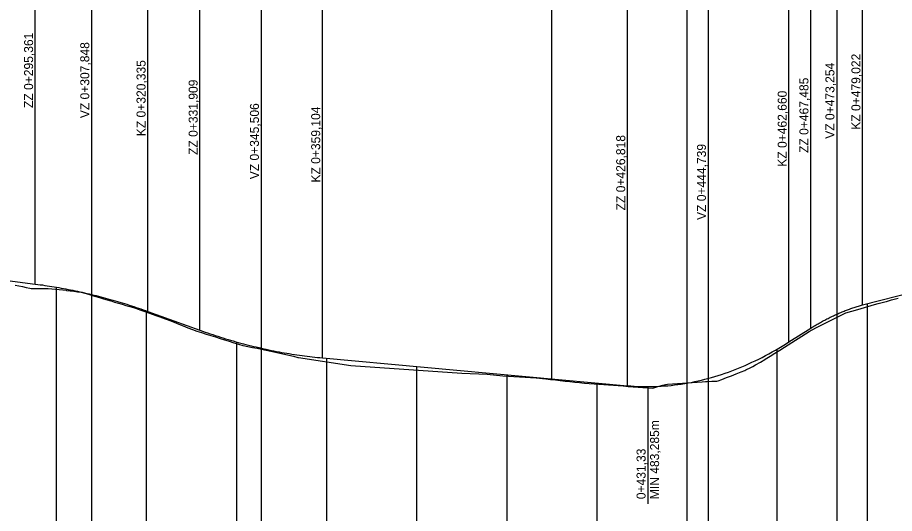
# Model space of a CAD drawing. Extents: x -632716 to -629545, y -1094726 to -1088285.
# Drawn here: x -632192 to -631997.4, y -1090910.5 to -1090800.4 of the extents above; entities that cross this region are included whole.
import ezdxf

# ---------------------------------------------------------------- set-up
doc = ezdxf.new("R2010")
doc.units = 0
for name, color, linetype in [('20', 7, 'Continuous'), ('Default', 7, 'Continuous'), ('SKLONY_NIVELETA', 7, 'Continuous'), ('SKLONY_POPIS', 7, 'Continuous'), ('TECNY_NIVELETA', 7, 'Continuous'), ('VOZOVKA', 7, 'Continuous')]:
    doc.layers.add(name, color=color, linetype=linetype)

msp = doc.modelspace()

# ---------------------------------------------------------------- linework, layer by layer
at = {"layer": '20'}
for points in [[(-632183.46, -1090860.27), (-632183.46, -1090965.2), (-632183.46, -1091015.2), (-632183.46, -1090955.2)], [(-632163.46, -1090865.55), (-632163.46, -1090965.2), (-632163.46, -1091015.2), (-632163.46, -1090955.2)], [(-632003.46, -1090863.98), (-632003.46, -1090965.2), (-632003.46, -1091015.2), (-632003.46, -1090955.2)], [(-632143.46, -1090872.42), (-632143.46, -1090965.2), (-632143.46, -1091015.2), (-632143.46, -1090955.2)], [(-632023.46, -1090874.05), (-632023.46, -1090965.2), (-632023.46, -1091015.2), (-632023.46, -1090955.2)], [(-632123.46, -1090876.05), (-632123.46, -1090965.2), (-632123.46, -1091015.2), (-632123.46, -1090955.2)], [(-632103.46, -1090877.87), (-632103.46, -1090965.2), (-632103.46, -1091015.2), (-632103.46, -1090955.2)], [(-632083.46, -1090879.7), (-632083.46, -1090965.2), (-632083.46, -1091015.2), (-632083.46, -1090955.2)], [(-632063.46, -1090881.52), (-632063.46, -1090965.2), (-632063.46, -1091015.2), (-632063.46, -1090955.2)], [(-632043.46, -1090881.59), (-632043.46, -1090965.2), (-632043.46, -1091015.2), (-632043.46, -1090955.2)]]:
    msp.add_lwpolyline(points, dxfattribs=at)
at = {"layer": 'Default'}
for p, q in [((-632320.69, -1090842.77), (-632188.1, -1090859.58)), ((-632320.69, -1090842.77), (-632188.1, -1090859.58)), ((-632004.44, -1090864.23), (-631946.1, -1090848.93)), ((-632004.44, -1090864.23), (-631946.1, -1090848.93)), ((-632163.13, -1090865.67), (-632151.56, -1090869.83)), ((-632163.13, -1090865.67), (-632151.56, -1090869.83)), ((-632020.8, -1090872.44), (-632015.98, -1090869.39)), ((-632020.8, -1090872.44), (-632015.98, -1090869.39)), ((-632124.36, -1090875.97), (-632056.65, -1090882.14)), ((-632124.36, -1090875.97), (-632056.65, -1090882.14))]:
    msp.add_line(p, q, dxfattribs=at)
for points in [[(-632188.1, -1090859.58), (-632187.58, -1090859.65), (-632187.06, -1090859.72), (-632186.54, -1090859.79), (-632186.02, -1090859.87), (-632185.5, -1090859.95), (-632184.98, -1090860.03), (-632184.46, -1090860.11), (-632183.94, -1090860.19), (-632183.42, -1090860.28), (-632182.9, -1090860.37), (-632182.38, -1090860.46), (-632181.86, -1090860.56), (-632181.34, -1090860.66), (-632180.82, -1090860.76), (-632180.3, -1090860.86), (-632179.78, -1090860.96), (-632179.26, -1090861.07), (-632178.74, -1090861.18), (-632178.22, -1090861.29), (-632177.7, -1090861.41), (-632177.18, -1090861.53), (-632176.66, -1090861.65), (-632176.14, -1090861.77), (-632175.1, -1090862.02), (-632174.58, -1090862.15), (-632174.06, -1090862.29), (-632173.53, -1090862.42), (-632173.01, -1090862.56), (-632172.49, -1090862.7), (-632171.97, -1090862.84), (-632171.45, -1090862.99), (-632170.93, -1090863.14), (-632170.41, -1090863.29), (-632169.89, -1090863.44), (-632169.37, -1090863.6), (-632168.85, -1090863.76), (-632168.33, -1090863.92), (-632167.81, -1090864.08), (-632167.29, -1090864.25), (-632166.77, -1090864.42), (-632166.25, -1090864.59), (-632165.73, -1090864.76), (-632165.21, -1090864.94), (-632164.69, -1090865.11), (-632164.17, -1090865.3), (-632163.65, -1090865.48), (-632163.13, -1090865.67)], [(-632188.1, -1090859.58), (-632187.58, -1090859.65), (-632187.06, -1090859.72), (-632186.54, -1090859.79), (-632186.02, -1090859.87), (-632185.5, -1090859.95), (-632184.98, -1090860.03), (-632184.46, -1090860.11), (-632183.94, -1090860.19), (-632183.42, -1090860.28), (-632182.9, -1090860.37), (-632182.38, -1090860.46), (-632181.86, -1090860.56), (-632181.34, -1090860.66), (-632180.82, -1090860.76), (-632180.3, -1090860.86), (-632179.78, -1090860.96), (-632179.26, -1090861.07), (-632178.74, -1090861.18), (-632178.22, -1090861.29), (-632177.7, -1090861.41), (-632177.18, -1090861.53), (-632176.66, -1090861.65), (-632176.14, -1090861.77), (-632175.1, -1090862.02), (-632174.58, -1090862.15), (-632174.06, -1090862.29), (-632173.53, -1090862.42), (-632173.01, -1090862.56), (-632172.49, -1090862.7), (-632171.97, -1090862.84), (-632171.45, -1090862.99), (-632170.93, -1090863.14), (-632170.41, -1090863.29), (-632169.89, -1090863.44), (-632169.37, -1090863.6), (-632168.85, -1090863.76), (-632168.33, -1090863.92), (-632167.81, -1090864.08), (-632167.29, -1090864.25), (-632166.77, -1090864.42), (-632166.25, -1090864.59), (-632165.73, -1090864.76), (-632165.21, -1090864.94), (-632164.69, -1090865.11), (-632164.17, -1090865.3), (-632163.65, -1090865.48), (-632163.13, -1090865.67)], [(-632015.98, -1090869.39), (-632015.74, -1090869.24), (-632015.5, -1090869.09), (-632015.26, -1090868.95), (-632015.02, -1090868.8), (-632014.78, -1090868.66), (-632014.54, -1090868.52), (-632014.3, -1090868.38), (-632014.06, -1090868.24), (-632013.82, -1090868.1), (-632013.57, -1090867.97), (-632013.33, -1090867.83), (-632013.09, -1090867.7), (-632012.85, -1090867.58), (-632012.61, -1090867.45), (-632012.37, -1090867.32), (-632012.13, -1090867.2), (-632011.89, -1090867.08), (-632011.65, -1090866.96), (-632011.41, -1090866.84), (-632011.17, -1090866.73), (-632010.93, -1090866.61), (-632010.69, -1090866.5), (-632010.45, -1090866.39), (-632009.97, -1090866.17), (-632009.73, -1090866.07), (-632009.49, -1090865.97), (-632009.25, -1090865.87), (-632009.01, -1090865.77), (-632008.77, -1090865.67), (-632008.53, -1090865.57), (-632008.29, -1090865.48), (-632008.05, -1090865.39), (-632007.81, -1090865.3), (-632007.57, -1090865.21), (-632007.33, -1090865.12), (-632007.09, -1090865.04), (-632006.84, -1090864.96), (-632006.6, -1090864.88), (-632006.36, -1090864.8), (-632006.12, -1090864.72), (-632005.88, -1090864.65), (-632005.64, -1090864.57), (-632005.4, -1090864.5), (-632005.16, -1090864.43), (-632004.92, -1090864.36), (-632004.68, -1090864.3), (-632004.44, -1090864.23)], [(-632015.98, -1090869.39), (-632015.74, -1090869.24), (-632015.5, -1090869.09), (-632015.26, -1090868.95), (-632015.02, -1090868.8), (-632014.78, -1090868.66), (-632014.54, -1090868.52), (-632014.3, -1090868.38), (-632014.06, -1090868.24), (-632013.82, -1090868.1), (-632013.57, -1090867.97), (-632013.33, -1090867.83), (-632013.09, -1090867.7), (-632012.85, -1090867.58), (-632012.61, -1090867.45), (-632012.37, -1090867.32), (-632012.13, -1090867.2), (-632011.89, -1090867.08), (-632011.65, -1090866.96), (-632011.41, -1090866.84), (-632011.17, -1090866.73), (-632010.93, -1090866.61), (-632010.69, -1090866.5), (-632010.45, -1090866.39), (-632009.97, -1090866.17), (-632009.73, -1090866.07), (-632009.49, -1090865.97), (-632009.25, -1090865.87), (-632009.01, -1090865.77), (-632008.77, -1090865.67), (-632008.53, -1090865.57), (-632008.29, -1090865.48), (-632008.05, -1090865.39), (-632007.81, -1090865.3), (-632007.57, -1090865.21), (-632007.33, -1090865.12), (-632007.09, -1090865.04), (-632006.84, -1090864.96), (-632006.6, -1090864.88), (-632006.36, -1090864.8), (-632006.12, -1090864.72), (-632005.88, -1090864.65), (-632005.64, -1090864.57), (-632005.4, -1090864.5), (-632005.16, -1090864.43), (-632004.92, -1090864.36), (-632004.68, -1090864.3), (-632004.44, -1090864.23)], [(-632151.56, -1090869.83), (-632150.99, -1090870.04), (-632150.42, -1090870.24), (-632149.86, -1090870.43), (-632149.29, -1090870.62), (-632148.72, -1090870.81), (-632148.16, -1090871), (-632147.59, -1090871.18), (-632147.02, -1090871.36), (-632146.46, -1090871.54), (-632145.89, -1090871.72), (-632145.32, -1090871.89), (-632144.76, -1090872.05), (-632144.19, -1090872.22), (-632143.62, -1090872.38), (-632143.06, -1090872.54), (-632142.49, -1090872.69), (-632141.92, -1090872.84), (-632141.36, -1090872.99), (-632140.79, -1090873.14), (-632140.22, -1090873.28), (-632139.66, -1090873.42), (-632139.09, -1090873.55), (-632138.52, -1090873.69), (-632137.39, -1090873.94), (-632136.82, -1090874.07), (-632136.26, -1090874.19), (-632135.69, -1090874.3), (-632135.12, -1090874.42), (-632134.56, -1090874.53), (-632133.99, -1090874.63), (-632133.43, -1090874.74), (-632132.86, -1090874.84), (-632132.29, -1090874.94), (-632131.73, -1090875.03), (-632131.16, -1090875.12), (-632130.59, -1090875.21), (-632130.03, -1090875.29), (-632129.46, -1090875.38), (-632128.89, -1090875.46), (-632128.33, -1090875.53), (-632127.76, -1090875.6), (-632127.19, -1090875.67), (-632126.63, -1090875.74), (-632126.06, -1090875.8), (-632125.49, -1090875.86), (-632124.93, -1090875.92), (-632124.36, -1090875.97)], [(-632151.56, -1090869.83), (-632150.99, -1090870.04), (-632150.42, -1090870.24), (-632149.86, -1090870.43), (-632149.29, -1090870.62), (-632148.72, -1090870.81), (-632148.16, -1090871), (-632147.59, -1090871.18), (-632147.02, -1090871.36), (-632146.46, -1090871.54), (-632145.89, -1090871.72), (-632145.32, -1090871.89), (-632144.76, -1090872.05), (-632144.19, -1090872.22), (-632143.62, -1090872.38), (-632143.06, -1090872.54), (-632142.49, -1090872.69), (-632141.92, -1090872.84), (-632141.36, -1090872.99), (-632140.79, -1090873.14), (-632140.22, -1090873.28), (-632139.66, -1090873.42), (-632139.09, -1090873.55), (-632138.52, -1090873.69), (-632137.39, -1090873.94), (-632136.82, -1090874.07), (-632136.26, -1090874.19), (-632135.69, -1090874.3), (-632135.12, -1090874.42), (-632134.56, -1090874.53), (-632133.99, -1090874.63), (-632133.43, -1090874.74), (-632132.86, -1090874.84), (-632132.29, -1090874.94), (-632131.73, -1090875.03), (-632131.16, -1090875.12), (-632130.59, -1090875.21), (-632130.03, -1090875.29), (-632129.46, -1090875.38), (-632128.89, -1090875.46), (-632128.33, -1090875.53), (-632127.76, -1090875.6), (-632127.19, -1090875.67), (-632126.63, -1090875.74), (-632126.06, -1090875.8), (-632125.49, -1090875.86), (-632124.93, -1090875.92), (-632124.36, -1090875.97)], [(-632056.65, -1090882.14), (-632055.9, -1090882.2), (-632055.15, -1090882.25), (-632054.41, -1090882.29), (-632053.66, -1090882.32), (-632052.91, -1090882.34), (-632052.17, -1090882.34), (-632051.42, -1090882.34), (-632050.67, -1090882.32), (-632049.93, -1090882.29), (-632049.18, -1090882.26), (-632048.43, -1090882.21), (-632047.69, -1090882.14), (-632046.94, -1090882.07), (-632046.19, -1090881.99), (-632045.45, -1090881.89), (-632044.7, -1090881.79), (-632043.95, -1090881.67), (-632043.21, -1090881.54), (-632042.46, -1090881.4), (-632041.71, -1090881.25), (-632040.97, -1090881.09), (-632040.22, -1090880.91), (-632039.47, -1090880.73), (-632037.98, -1090880.32), (-632037.23, -1090880.1), (-632036.48, -1090879.87), (-632035.74, -1090879.63), (-632034.99, -1090879.38), (-632034.24, -1090879.12), (-632033.5, -1090878.84), (-632032.75, -1090878.56), (-632032, -1090878.26), (-632031.26, -1090877.95), (-632030.51, -1090877.63), (-632029.76, -1090877.3), (-632029.02, -1090876.95), (-632028.27, -1090876.6), (-632027.52, -1090876.24), (-632026.78, -1090875.86), (-632026.03, -1090875.47), (-632025.28, -1090875.07), (-632024.54, -1090874.66), (-632023.79, -1090874.24), (-632023.04, -1090873.81), (-632022.3, -1090873.37), (-632021.55, -1090872.91), (-632020.8, -1090872.44)], [(-632056.65, -1090882.14), (-632055.9, -1090882.2), (-632055.15, -1090882.25), (-632054.41, -1090882.29), (-632053.66, -1090882.32), (-632052.91, -1090882.34), (-632052.17, -1090882.34), (-632051.42, -1090882.34), (-632050.67, -1090882.32), (-632049.93, -1090882.29), (-632049.18, -1090882.26), (-632048.43, -1090882.21), (-632047.69, -1090882.14), (-632046.94, -1090882.07), (-632046.19, -1090881.99), (-632045.45, -1090881.89), (-632044.7, -1090881.79), (-632043.95, -1090881.67), (-632043.21, -1090881.54), (-632042.46, -1090881.4), (-632041.71, -1090881.25), (-632040.97, -1090881.09), (-632040.22, -1090880.91), (-632039.47, -1090880.73), (-632037.98, -1090880.32), (-632037.23, -1090880.1), (-632036.48, -1090879.87), (-632035.74, -1090879.63), (-632034.99, -1090879.38), (-632034.24, -1090879.12), (-632033.5, -1090878.84), (-632032.75, -1090878.56), (-632032, -1090878.26), (-632031.26, -1090877.95), (-632030.51, -1090877.63), (-632029.76, -1090877.3), (-632029.02, -1090876.95), (-632028.27, -1090876.6), (-632027.52, -1090876.24), (-632026.78, -1090875.86), (-632026.03, -1090875.47), (-632025.28, -1090875.07), (-632024.54, -1090874.66), (-632023.79, -1090874.24), (-632023.04, -1090873.81), (-632022.3, -1090873.37), (-632021.55, -1090872.91), (-632020.8, -1090872.44)]]:
    msp.add_lwpolyline(points, dxfattribs=at)
at = {"layer": 'SKLONY_NIVELETA'}
for p, q in [((-632043.46, -1090722.19), (-632043.46, -1090881.59)), ((-632175.62, -1090761.17), (-632175.62, -1091015.2)), ((-632010.21, -1090765.75), (-632010.21, -1091015.2)), ((-632137.96, -1090774.73), (-632137.96, -1091015.2)), ((-632038.72, -1090783.77), (-632038.72, -1091015.2)), ((-632320.69, -1090842.77), (-632188.1, -1090859.58)), ((-632004.44, -1090864.23), (-631946.1, -1090848.93)), ((-632163.13, -1090865.67), (-632151.56, -1090869.83)), ((-632020.8, -1090872.44), (-632015.98, -1090869.39)), ((-632124.36, -1090875.97), (-632056.65, -1090882.14))]:
    msp.add_line(p, q, dxfattribs=at)
for points in [[(-632188.1, -1090859.58), (-632187.58, -1090859.65), (-632187.06, -1090859.72), (-632186.54, -1090859.79), (-632186.02, -1090859.87), (-632185.5, -1090859.95), (-632184.98, -1090860.03), (-632184.46, -1090860.11), (-632183.94, -1090860.19), (-632183.42, -1090860.28), (-632182.9, -1090860.37), (-632182.38, -1090860.46), (-632181.86, -1090860.56), (-632181.34, -1090860.66), (-632180.82, -1090860.76), (-632180.3, -1090860.86), (-632179.78, -1090860.96), (-632179.26, -1090861.07), (-632178.74, -1090861.18), (-632178.22, -1090861.29), (-632177.7, -1090861.41), (-632177.18, -1090861.53), (-632176.66, -1090861.65), (-632176.14, -1090861.77), (-632175.1, -1090862.02), (-632174.58, -1090862.15), (-632174.06, -1090862.29), (-632173.53, -1090862.42), (-632173.01, -1090862.56), (-632172.49, -1090862.7), (-632171.97, -1090862.84), (-632171.45, -1090862.99), (-632170.93, -1090863.14), (-632170.41, -1090863.29), (-632169.89, -1090863.44), (-632169.37, -1090863.6), (-632168.85, -1090863.76), (-632168.33, -1090863.92), (-632167.81, -1090864.08), (-632167.29, -1090864.25), (-632166.77, -1090864.42), (-632166.25, -1090864.59), (-632165.73, -1090864.76), (-632165.21, -1090864.94), (-632164.69, -1090865.11), (-632164.17, -1090865.3), (-632163.65, -1090865.48), (-632163.13, -1090865.67)], [(-632015.98, -1090869.39), (-632015.74, -1090869.24), (-632015.5, -1090869.09), (-632015.26, -1090868.95), (-632015.02, -1090868.8), (-632014.78, -1090868.66), (-632014.54, -1090868.52), (-632014.3, -1090868.38), (-632014.06, -1090868.24), (-632013.82, -1090868.1), (-632013.57, -1090867.97), (-632013.33, -1090867.83), (-632013.09, -1090867.7), (-632012.85, -1090867.58), (-632012.61, -1090867.45), (-632012.37, -1090867.32), (-632012.13, -1090867.2), (-632011.89, -1090867.08), (-632011.65, -1090866.96), (-632011.41, -1090866.84), (-632011.17, -1090866.73), (-632010.93, -1090866.61), (-632010.69, -1090866.5), (-632010.45, -1090866.39), (-632009.97, -1090866.17), (-632009.73, -1090866.07), (-632009.49, -1090865.97), (-632009.25, -1090865.87), (-632009.01, -1090865.77), (-632008.77, -1090865.67), (-632008.53, -1090865.57), (-632008.29, -1090865.48), (-632008.05, -1090865.39), (-632007.81, -1090865.3), (-632007.57, -1090865.21), (-632007.33, -1090865.12), (-632007.09, -1090865.04), (-632006.84, -1090864.96), (-632006.6, -1090864.88), (-632006.36, -1090864.8), (-632006.12, -1090864.72), (-632005.88, -1090864.65), (-632005.64, -1090864.57), (-632005.4, -1090864.5), (-632005.16, -1090864.43), (-632004.92, -1090864.36), (-632004.68, -1090864.3), (-632004.44, -1090864.23)], [(-632151.56, -1090869.83), (-632150.99, -1090870.04), (-632150.42, -1090870.24), (-632149.86, -1090870.43), (-632149.29, -1090870.62), (-632148.72, -1090870.81), (-632148.16, -1090871), (-632147.59, -1090871.18), (-632147.02, -1090871.36), (-632146.46, -1090871.54), (-632145.89, -1090871.72), (-632145.32, -1090871.89), (-632144.76, -1090872.05), (-632144.19, -1090872.22), (-632143.62, -1090872.38), (-632143.06, -1090872.54), (-632142.49, -1090872.69), (-632141.92, -1090872.84), (-632141.36, -1090872.99), (-632140.79, -1090873.14), (-632140.22, -1090873.28), (-632139.66, -1090873.42), (-632139.09, -1090873.55), (-632138.52, -1090873.69), (-632137.39, -1090873.94), (-632136.82, -1090874.07), (-632136.26, -1090874.19), (-632135.69, -1090874.3), (-632135.12, -1090874.42), (-632134.56, -1090874.53), (-632133.99, -1090874.63), (-632133.43, -1090874.74), (-632132.86, -1090874.84), (-632132.29, -1090874.94), (-632131.73, -1090875.03), (-632131.16, -1090875.12), (-632130.59, -1090875.21), (-632130.03, -1090875.29), (-632129.46, -1090875.38), (-632128.89, -1090875.46), (-632128.33, -1090875.53), (-632127.76, -1090875.6), (-632127.19, -1090875.67), (-632126.63, -1090875.74), (-632126.06, -1090875.8), (-632125.49, -1090875.86), (-632124.93, -1090875.92), (-632124.36, -1090875.97)], [(-632056.65, -1090882.14), (-632055.9, -1090882.2), (-632055.15, -1090882.25), (-632054.41, -1090882.29), (-632053.66, -1090882.32), (-632052.91, -1090882.34), (-632052.17, -1090882.34), (-632051.42, -1090882.34), (-632050.67, -1090882.32), (-632049.93, -1090882.29), (-632049.18, -1090882.26), (-632048.43, -1090882.21), (-632047.69, -1090882.14), (-632046.94, -1090882.07), (-632046.19, -1090881.99), (-632045.45, -1090881.89), (-632044.7, -1090881.79), (-632043.95, -1090881.67), (-632043.21, -1090881.54), (-632042.46, -1090881.4), (-632041.71, -1090881.25), (-632040.97, -1090881.09), (-632040.22, -1090880.91), (-632039.47, -1090880.73), (-632037.98, -1090880.32), (-632037.23, -1090880.1), (-632036.48, -1090879.87), (-632035.74, -1090879.63), (-632034.99, -1090879.38), (-632034.24, -1090879.12), (-632033.5, -1090878.84), (-632032.75, -1090878.56), (-632032, -1090878.26), (-632031.26, -1090877.95), (-632030.51, -1090877.63), (-632029.76, -1090877.3), (-632029.02, -1090876.95), (-632028.27, -1090876.6), (-632027.52, -1090876.24), (-632026.78, -1090875.86), (-632026.03, -1090875.47), (-632025.28, -1090875.07), (-632024.54, -1090874.66), (-632023.79, -1090874.24), (-632023.04, -1090873.81), (-632022.3, -1090873.37), (-632021.55, -1090872.91), (-632020.8, -1090872.44)]]:
    msp.add_lwpolyline(points, dxfattribs=at)
at = {"layer": 'TECNY_NIVELETA'}
for p, q in [((-632073.46, -1090880.61), (-632073.46, -1090714.82)), ((-632188.1, -1090859.58), (-632188.1, -1090758.58)), ((-632004.44, -1090864.23), (-632004.44, -1090763.23)), ((-632163.13, -1090865.67), (-632163.13, -1090764.67)), ((-632015.98, -1090869.39), (-632015.98, -1090768.39)), ((-632151.56, -1090869.83), (-632151.56, -1090768.83)), ((-632020.8, -1090872.44), (-632020.8, -1090771.44)), ((-632124.36, -1090875.97), (-632124.36, -1090774.97)), ((-632056.65, -1090882.14), (-632056.65, -1090781.14)), ((-632052.13, -1090882.34), (-632052.13, -1090908.34))]:
    msp.add_line(p, q, dxfattribs=at)
at = {"layer": 'VOZOVKA'}
msp.add_lwpolyline([(-632192.56, -1090859.8), (-632191.75, -1090859.97), (-632190.94, -1090860.16), (-632190.12, -1090860.34), (-632189.31, -1090860.53), (-632189.05, -1090860.6), (-632188.5, -1090860.59), (-632187.68, -1090860.58), (-632186.87, -1090860.57), (-632186.06, -1090860.56), (-632185.28, -1090860.55), (-632185.25, -1090860.55), (-632184.43, -1090860.64), (-632183.62, -1090860.73), (-632182.81, -1090860.81), (-632181.99, -1090860.9), (-632181.29, -1090860.97), (-632181.18, -1090860.99), (-632180.37, -1090861.09), (-632179.55, -1090861.19), (-632178.74, -1090861.29), (-632177.93, -1090861.39), (-632177.89, -1090861.4), (-632177.11, -1090861.62), (-632176.3, -1090861.86), (-632175.49, -1090862.1), (-632174.65, -1090862.35), (-632173.82, -1090862.59), (-632172.99, -1090862.83), (-632172.15, -1090863.08), (-632171.32, -1090863.32), (-632171.25, -1090863.34), (-632170.49, -1090863.57), (-632169.65, -1090863.81), (-632168.82, -1090864.06), (-632167.99, -1090864.31), (-632167.15, -1090864.55), (-632166.32, -1090864.8), (-632165.65, -1090865), (-632165.49, -1090865.05), (-632164.65, -1090865.35), (-632163.82, -1090865.65), (-632162.99, -1090865.95), (-632162.15, -1090866.25), (-632161.32, -1090866.55), (-632160.49, -1090866.85), (-632159.27, -1090867.28), (-632159.02, -1090867.37), (-632158.27, -1090867.67), (-632157.27, -1090868.07), (-632156.27, -1090868.47), (-632155.27, -1090868.87), (-632154.27, -1090869.27), (-632153.24, -1090869.67), (-632153.2, -1090869.69), (-632152.22, -1090870.01), (-632151.19, -1090870.34), (-632150.17, -1090870.67), (-632149.14, -1090870.99), (-632148.12, -1090871.32), (-632147.09, -1090871.64), (-632146.07, -1090871.96), (-632145.04, -1090872.28), (-632144.02, -1090872.6), (-632142.99, -1090872.92), (-632142, -1090873.23), (-632141.97, -1090873.23), (-632140.94, -1090873.44), (-632139.92, -1090873.64), (-632138.89, -1090873.85), (-632137.86, -1090874.06), (-632136.84, -1090874.28), (-632135.81, -1090874.5), (-632134.79, -1090874.73), (-632133.79, -1090874.95), (-632132.79, -1090875.17), (-632131.79, -1090875.4), (-632130.79, -1090875.62), (-632129.79, -1090875.85), (-632129.68, -1090875.87), (-632118.08, -1090877.68), (-632093.41, -1090879.36), (-632087.8, -1090879.58), (-632084.31, -1090879.96), (-632076.95, -1090880.39), (-632074.78, -1090880.63), (-632073.71, -1090880.75), (-632072.64, -1090880.87), (-632071.57, -1090880.99), (-632070.49, -1090881.11), (-632069.42, -1090881.23), (-632068.35, -1090881.35), (-632067.28, -1090881.46), (-632066.8, -1090881.51), (-632066.21, -1090881.56), (-632065.14, -1090881.64), (-632064.07, -1090881.73), (-632062.99, -1090881.81), (-632061.92, -1090881.89), (-632060.85, -1090881.97), (-632059.78, -1090882.05), (-632058.69, -1090882.13), (-632057.59, -1090882.21), (-632056.5, -1090882.29), (-632055.4, -1090882.37), (-632054.31, -1090882.44), (-632053.21, -1090882.52), (-632052.12, -1090882.6), (-632051.04, -1090882.67), (-632051.02, -1090882.67), (-632049.93, -1090882.35), (-632048.83, -1090882.04), (-632048.21, -1090881.85), (-632047.74, -1090881.82), (-632046.64, -1090881.75), (-632045.55, -1090881.67), (-632044.45, -1090881.59), (-632043.36, -1090881.52), (-632042.26, -1090881.44), (-632041.17, -1090881.37), (-632040.07, -1090881.29), (-632039.32, -1090881.24), (-632038.98, -1090881.22), (-632037.89, -1090881.17), (-632036.79, -1090881.11), (-632036.52, -1090881.1), (-632035.72, -1090880.78), (-632034.65, -1090880.35), (-632033.58, -1090879.93), (-632032.5, -1090879.51), (-632031.43, -1090879.09), (-632030.63, -1090878.77), (-632030.36, -1090878.64), (-632029.29, -1090878.13), (-632028.83, -1090877.91), (-632028.22, -1090877.54), (-632027.15, -1090876.89), (-632026.17, -1090876.3), (-632026.08, -1090876.24), (-632025, -1090875.57), (-632023.93, -1090874.9), (-632022.86, -1090874.23), (-632021.79, -1090873.56), (-632016.31, -1090870.13), (-632014.8, -1090869.33), (-632008.14, -1090865.97), (-632005.53, -1090865.21), (-632004.03, -1090864.77), (-632002.53, -1090864.33), (-632002.32, -1090864.27), (-632001.03, -1090863.93), (-631999.53, -1090863.53), (-631999.13, -1090863.43), (-631998.03, -1090863.11), (-631996.53, -1090862.68)], dxfattribs=at)

# ---------------------------------------------------------------- texts
at = {"layer": 'SKLONY_POPIS'}
for s, p in [('ZZ 0+295,361', (-632188.6, -1090820.5)), ('VZ 0+307,848', (-632176.12, -1090822.75)), ('KZ 0+479,022', (-632004.94, -1090825.32)), ('KZ 0+320,335', (-632163.63, -1090826.75)), ('VZ 0+473,254', (-632010.71, -1090827.33)), ('ZZ 0+331,909', (-632152.06, -1090830.92)), ('ZZ 0+467,485', (-632016.48, -1090830.48)), ('KZ 0+462,660', (-632021.3, -1090833.53)), ('VZ 0+345,506', (-632138.46, -1090836.31)), ('KZ 0+359,104', (-632124.86, -1090837.05)), ('ZZ 0+426,818', (-632057.15, -1090843.22)), ('VZ 0+444,739', (-632039.22, -1090845.35)), ('MIN 483,285m', (-632049.63, -1090907.34)), ('0+431,33', (-632052.63, -1090907.34))]:
    msp.add_text(s, height=2, rotation=90, dxfattribs=at).set_placement(p)

doc.saveas('drawing.dxf')
